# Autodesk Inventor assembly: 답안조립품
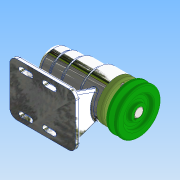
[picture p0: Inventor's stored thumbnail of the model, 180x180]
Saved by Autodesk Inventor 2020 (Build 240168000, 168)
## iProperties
Created: 2021-10
Part Number: 답안조립품
Document SubType Name: Assembly
Designer: user
Author: user
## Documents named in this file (12)
- C:\Users\user\Desktop\711007V1017\답안조립품.iam
- C:\Users\user\Desktop\711007V1017\V벨트풀리.ipt
- C:\Users\user\Desktop\711007V1017\멈춤나사 M3.ipt
- C:\Users\user\Desktop\711007V1017\베어링 6004.ipt
- C:\Users\user\Desktop\711007V1017\베어링 51202.ipt
- C:\Users\user\Desktop\711007V1017\본체.ipt
- C:\Users\user\Desktop\711007V1017\볼트 M4.ipt
- C:\Users\user\Desktop\711007V1017\어댑터슬리브.ipt
- C:\Users\user\Desktop\711007V1017\오일 실 20x35x7.ipt
- C:\Users\user\Desktop\711007V1017\축.ipt
- C:\Users\user\Desktop\711007V1017\커버.ipt
- C:\Users\user\Desktop\711007V1017\키 5x5.ipt
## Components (1 placed, 1 different names)
1. V벨트풀리:1
